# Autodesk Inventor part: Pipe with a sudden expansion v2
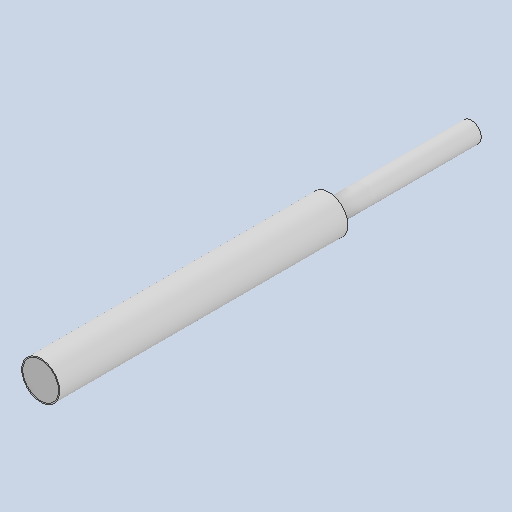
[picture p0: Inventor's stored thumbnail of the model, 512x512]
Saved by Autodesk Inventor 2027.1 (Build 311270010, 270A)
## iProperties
Created: 2026-10
Part Number: Pipe with a sudden expansion v2
Material: Generic
Document SubType Name: Modeling
Designer: niels
Density: 1 g/cm^3
Appearance: Default
Author: niels
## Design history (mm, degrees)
sketch "Sketch1"
  geometry: L1 (-25, 0)-(-28, 0); L2 (-28, 0)-(-28, 397); L3 (-28, 397)-(-53, 397); L4 (-53, 397)-(-53, 1200); L5 (-53, 1200)-(-50, 1200); L6 (-50, 1200)-(-50, 400); L7 (-50, 400)-(-25, 400); L8 (-25, 400)-(-25, 0); L9 (0, -240)-(0, 1440) reference
  constraints: 16 end point
revolve "Revolution1" sketch "Sketch1" stored, may be unused: angle "d0" = 0 deg
sketch "Sketch2"
  geometry: L1 (0, 0)-(-25, 0); L2 (-25, 0)-(-25, 400); L3 (-25, 400)-(-50, 400); L4 (-50, 400)-(-50, 1200); L5 (-50, 1200)-(0, 1200); L6 (0, 1200)-(0, 0); L7 (0, -240)-(0, 1440) reference
  constraints: 12 end point
revolve "Revolution2" sketch "Sketch2" stored, may be unused: angle "d1" = 0 deg
node "Pipe"
node "Air"
